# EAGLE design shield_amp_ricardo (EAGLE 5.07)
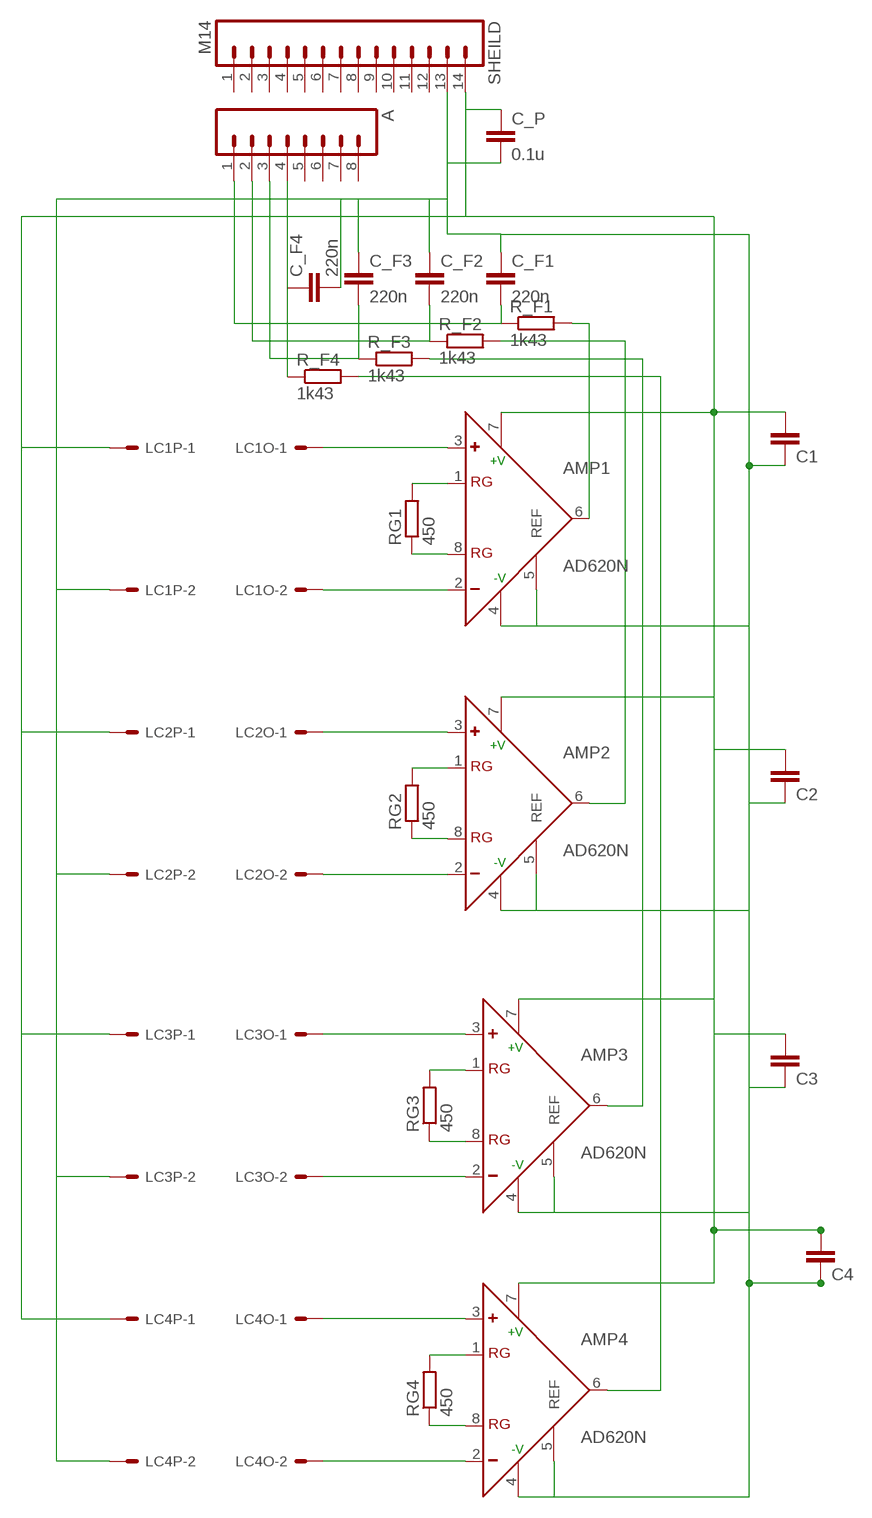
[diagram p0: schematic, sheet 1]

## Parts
A  M081X08  [1X08]
AMP1  AD620N  [DIL08]
AMP2  AD620N  [DIL08]
AMP3  AD620N  [DIL08]
AMP4  AD620N  [DIL08]
C1  C-EUC0603  [C0603]
C2  C-EUC0603  [C0603]
C3  C-EUC0603  [C0603]
C4  C-EUC0603  [C0603]
C_F1  220n  C-EU025-024X044  [C025-024X044]
C_F2  220n  C-EU025-024X044  [C025-024X044]
C_F3  220n  C-EU025-024X044  [C025-024X044]
C_F4  220n  C-EU025-024X044  [C025-024X044]
C_P  0.1u  C-EU025-024X044  [C025-024X044]
LC1O  87758-0216  [87758-0216]
LC1P  87758-0216  [87758-0216]
LC2O  87758-0216  [87758-0216]
LC2P  87758-0216  [87758-0216]
LC3O  87758-0216  [87758-0216]
LC3P  87758-0216  [87758-0216]
LC4O  87758-0216  [87758-0216]
LC4P  87758-0216  [87758-0216]
R_F1  1k43  R-EU_0207/7  [0207/7]
R_F2  1k43  R-EU_0207/7  [0207/7]
R_F3  1k43  R-EU_0207/7  [0207/7]
R_F4  1k43  R-EU_0207/7  [0207/7]
RG1  450  R-EU_0207/7  [0207/7]
RG2  450  R-EU_0207/7  [0207/7]
RG3  450  R-EU_0207/7  [0207/7]
RG4  450  R-EU_0207/7  [0207/7]
SHEILD  M14  [1X14]

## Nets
GND: AMP1.4(-V) AMP1.5(REF) AMP2.4(-V) AMP2.5(REF) AMP3.4(-V) AMP3.5(REF) AMP4.4(-V) AMP4.5(REF) C1.1 C2.1 C3.1 C4.1 C_F1.1 C_F2.1 C_F3.1 C_F4.2 C_P.2 LC1P.2 LC2P.2 LC3P.2 LC4P.2 SHEILD.13
N$1: AMP1.1(RG) RG1.2
N$2: AMP1.3(+) LC1O.1
N$3: AMP1.8(RG) RG1.1
N$4: AMP1.2(-) LC1O.2
N$5: AMP2.3(+) LC2O.1
N$6: AMP2.1(RG) RG2.2
N$7: AMP2.8(RG) RG2.1
N$8: AMP2.2(-) LC2O.2
N$9: AMP3.3(+) LC3O.1
N$10: AMP3.1(RG) RG3.2
N$11: AMP3.8(RG) RG3.1
N$12: AMP3.2(-) LC3O.2
N$13: AMP4.3(+) LC4O.1
N$14: AMP4.1(RG) RG4.2
N$15: AMP4.8(RG) RG4.1
N$16: AMP4.2(-) LC4O.2
N$17: AMP1.6(OUT) R_F1.2
N$18: AMP2.6(OUT) R_F2.2
N$19: AMP3.6(OUT) R_F3.2
N$20: AMP4.6(OUT) R_F4.2
N$22: A.3 C_F3.2 R_F3.1
N$23: A.1 C_F1.2 R_F1.1
N$25: A.2 C_F2.2 R_F2.1
N$26: A.4 C_F4.1 R_F4.1
VCC: AMP1.7(+V) AMP2.7(+V) AMP3.7(+V) AMP4.7(+V) C1.2 C2.2 C3.2 C4.2 C_P.1 LC1P.1 LC2P.1 LC3P.1 LC4P.1 SHEILD.14
Unconnected: A.5 A.6 A.7 A.8 SHEILD.1 SHEILD.2 SHEILD.3 SHEILD.4 SHEILD.5 SHEILD.6 SHEILD.7 SHEILD.8 SHEILD.9 SHEILD.10 SHEILD.11 SHEILD.12

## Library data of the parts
A = SparkFun:M08: Header 8 Standard 8-pin 0.1" header. Use with straight break away headers (SKU : PRT-00116), right angle break away headers (PRT-00553), swiss pins (PRT-00743), machine pins (PRT-00117), and female headers (PRT-00115).
AMP1-AMP4 = analog-devices:AD620: Low Cost, Low Power, Instrumentation Amplifier Source: http://www.analog.com/UploadedFiles/Data_Sheets/37793330023930AD620_e.pdf
C1-C4 C_F1-C_F4 C_P = resistor:C-EU: CAPACITOR, European symbol
LC1O LC1P LC2O LC2P LC3O LC3P LC4O LC4P = con-molex:87758-0216: 2 Pin - 2mm Dual Row Single Wafer, Vertical T/H HDR
R_F1-R_F4 RG1-RG4 = resistor:R-EU_: RESISTOR, European symbol
SHEILD = SparkFun:M14: Header 14 Standard 14-pin 0.1" header. Use with straight break away headers (SKU : PRT-00116), right angle break away headers (PRT-00553), swiss pins (PRT-00743), machine pins (PRT-00117), and female headers (PRT-00115).

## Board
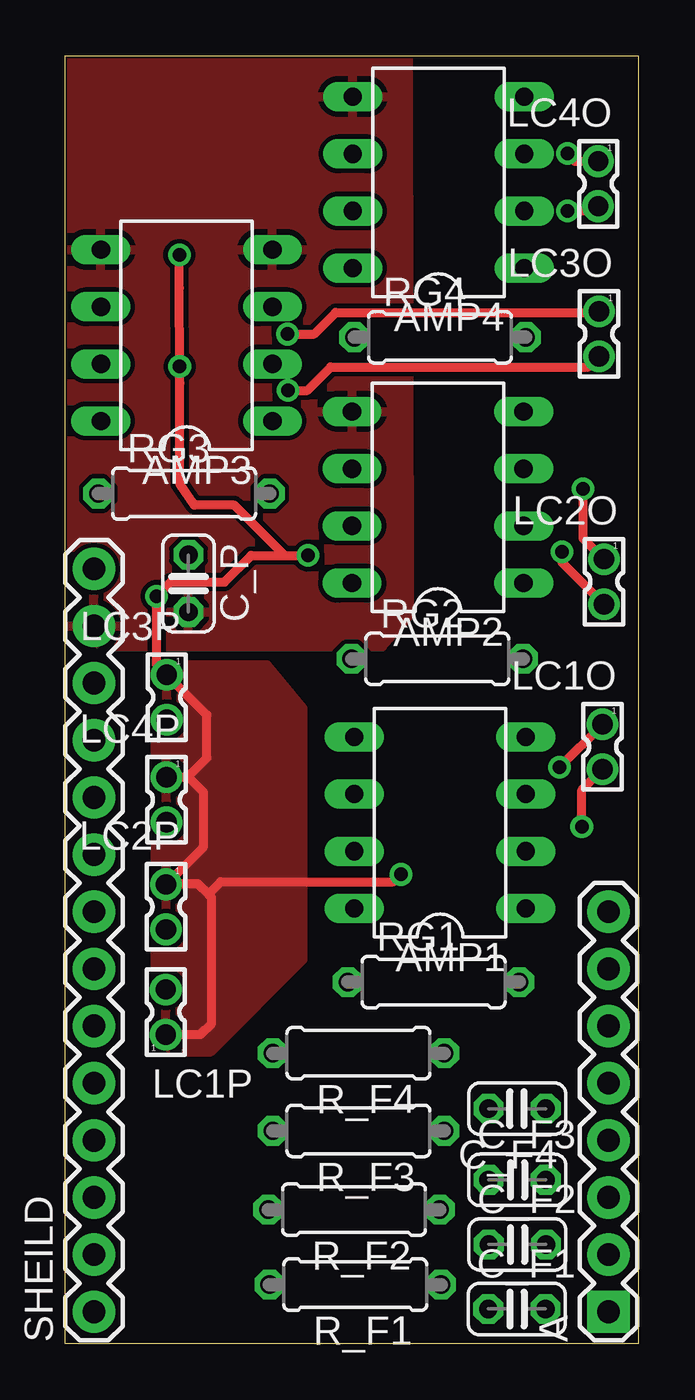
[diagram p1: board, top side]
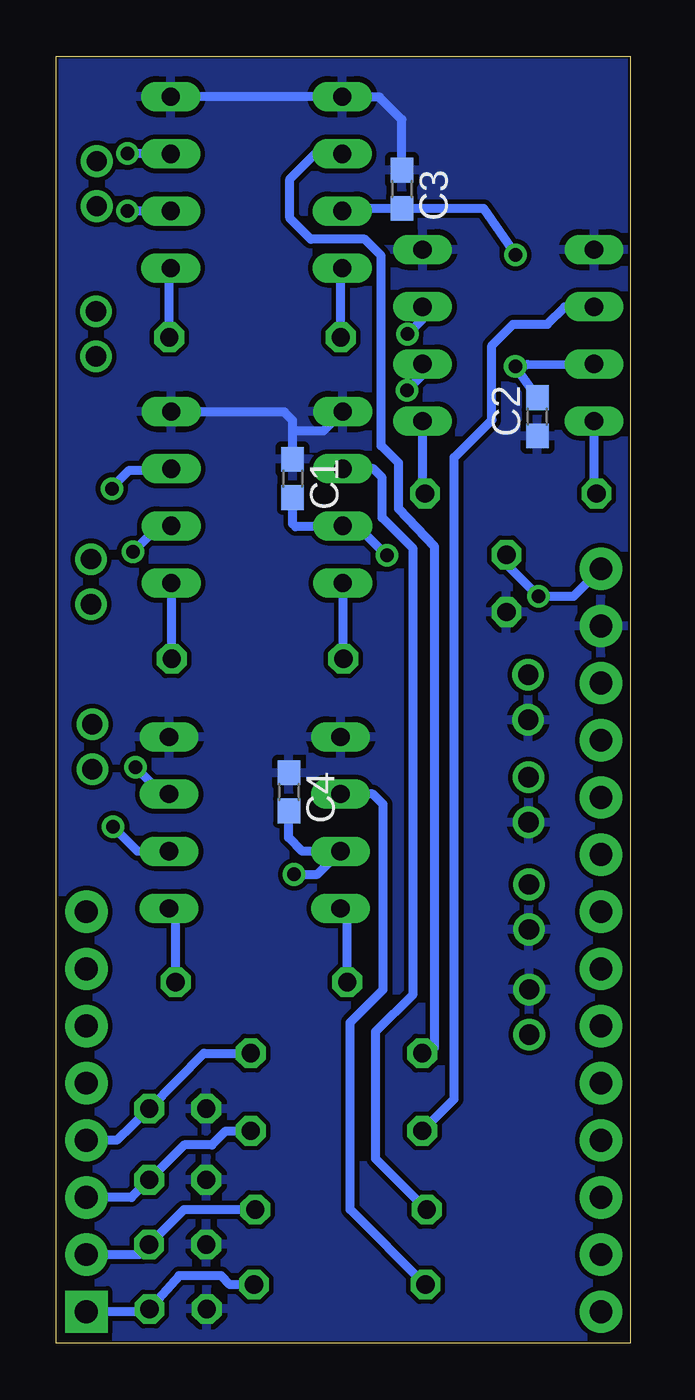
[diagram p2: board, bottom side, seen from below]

Size 25.5 x 57.2 mm. Coordinates in mm from the lower left corner, seen from the top.
Outline: 0,0 25.5,0 25.5,57.2 0,57.2 0,0
Copper layers (1*16): Top 0.035mm / dielectric 1.5mm / Bottom 0.035mm
Design rules "default *": minimum track width 10mil, minimum drill 24mil, track to track 8mil, track to pad 8mil, pad to pad 8mil, via to via 8mil, smd to smd 8mil, copper to edge 4mil, drill to drill 8mil, minimum pad ring 10mil, minimum via ring 8mil, stop-mask expansion 4mil, vias tented up to drill 0mil, thermal gap 10mil

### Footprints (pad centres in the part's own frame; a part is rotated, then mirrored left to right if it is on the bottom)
1X08 = drill 1.016 pad 1.88 square: 1 0,0 | drill 1.016 pad 1.88 round: 2 2.54,0; 3 5.08,0; 4 7.62,0; 5 10.16,0; 6 12.7,0; 7 15.24,0; 8 17.78,0
DIL08 = drill 0.813 long: 1 -3.81,-3.81; 2 -1.27,-3.81; 3 1.27,-3.81; 4 3.81,-3.81; 5 3.81,3.81; 6 1.27,3.81; 7 -1.27,3.81; 8 -3.81,3.81
C0603 = smd 1.1 x 1: 1 -0.85,0; 2 0.85,0
C025-024X044 = drill 0.813 octagon: 1 -1.27,0; 2 1.27,0
87758-0216 = drill 0.9 pad 1.27 round: 1 0,-1; 2 0,1
0207/7 = drill 0.813 octagon: 1 -3.81,0; 2 3.81,0
1X14 = drill 1.016 pad 1.88 round: 1 0,0; 2 2.54,0; 3 5.08,0; 4 7.62,0; 5 10.16,0; 6 12.7,0; 7 15.24,0; 8 17.78,0; 9 20.32,0; 10 22.86,0; 11 25.4,0; 12 27.94,0; 13 30.48,0; 14 33.02,0

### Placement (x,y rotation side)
A  24.16,1.4 90 top
AMP1  16.68,23.14 90 top
AMP2  16.58,37.6 90 top
AMP3  5.42,44.8 90 top
AMP4  16.6,51.59 90 top
C1  15,38.44 270 bottom
C2  4.13,41.18 90 bottom
C3  10.14,51.28 270 bottom
C4  15.17,24.5 270 bottom
C_F1  20.08,1.52 0 top
C_F2  20.11,4.39 0 top
C_F3  20.1,7.26 0 top
C_F4  20.1,10.43 180 top
C_P  5.5,33.77 270 top
LC1O  23.9,26.51 180 top
LC1P  4.49,14.72 0 top
LC2O  23.95,33.85 180 top
LC2P  4.5,19.4 180 top
LC3O  23.73,44.86 180 top
LC3P  4.53,28.71 180 top
LC4O  23.7,51.53 180 top
LC4P  4.52,24.15 180 top
R_F1  12.91,2.6 180 top
R_F2  12.85,5.94 180 top
R_F3  13.05,9.44 180 top
R_F4  13.05,12.89 180 top
RG1  16.39,16.05 0 top
RG2  16.55,30.42 0 top
RG3  5.3,37.76 0 top
RG4  16.67,44.71 0 top
SHEILD  1.3,1.4 90 top

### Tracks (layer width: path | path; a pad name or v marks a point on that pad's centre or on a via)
GND
  Top 0.406: C_F3.1 | C_F4.2
  Bottom 0.406: AMP2.5 13.62,40.56 14.88,40.56 15,40.44 | C1.1 15,40.44 | AMP2.4 20.37,41.39 15.37,41.39 15,41.02 15,40.44 | C3.1 10.14,54.39 11.14,55.39 AMP4.5 AMP4.4
  pour Bottom: -0.99,57.87 -1.12,57.87 -1.12,-1.16 26.14,-1.16 26.14,57.74
  pour Top: -0.55,57.58 -0.5,31.69 1.91,30.98 14.11,30.96 15.34,32.37 15.29,57.23 14.87,57.65
N$1
  Bottom 0.406: AMP1.1 20.2,19.04 RG1.2
N$2  (via drill 0.6)
  Top 0.406: v21.98,25.59 LC1O.1
  Bottom 0.406: v21.98,25.59 20.8,24.41 AMP1.3
N$3
  Bottom 0.406: AMP1.8 12.58,19.04 RG1.1
N$4  (via drill 0.6)
  Top 0.406: LC1O.2 22.97,24.59 v22.97,22.96
  Bottom 0.406: v22.97,22.96 21.88,21.87 AMP1.2
N$5  (via drill 0.6)
  Top 0.406: LC2O.1 23.03,35.77 v23.03,37.98
  Bottom 0.406: v23.03,37.98 23.03,38.03 22.26,38.8 20.46,38.8 AMP2.3
N$6
  Bottom 0.406: AMP2.1 20.37,33.76 RG2.2
N$7
  Bottom 0.406: AMP2.8 12.74,33.76 RG2.1
N$8  (via drill 0.6)
  Top 0.406: LC2O.2 22.1,34.71 v22.1,35.17
  Bottom 0.406: v22.1,35.17 20.94,36.33 AMP2.2
N$9  (via drill 0.6)
  Top 0.406: 23.52,46.07 LC3O.1 23.69,45.81 12.03,45.81 11.08,44.85 v9.89,44.85
  Bottom 0.406: AMP3.3 9.23,45.52 v9.89,44.85
N$10
  Bottom 0.406: AMP3.1 9.23,37.88 RG3.2
N$11
  Bottom 0.406: AMP3.8 1.6,37.88 RG3.1
N$12  (via drill 0.6)
  Top 0.406: 23.41,43.53 LC3O.2 23.27,43.39 11.81,43.39 10.77,42.34 v9.92,42.34
  Bottom 0.406: AMP3.2 9.23,43.04 v9.92,42.34
N$13  (via drill 0.6)
  Top 0.406: LC4O.1 22.68,52.53 v22.34,52.88
  Bottom 0.406: v22.34,52.88 20.43,52.88 AMP4.3
N$14
  Bottom 0.406: AMP4.1 20.48,47.71 RG4.2
N$15
  Bottom 0.406: AMP4.8 12.86,47.71 RG4.1
N$16  (via drill 0.6)
  Top 0.406: v22.34,50.33 23.49,50.33 LC4O.2
  Bottom 0.406: AMP4.2 v22.33,50.32 v22.34,50.33
N$17
  Bottom 0.406: AMP1.6 11.44,24.41 10.98,23.95 10.98,15.72 12.44,14.26 12.44,5.95 R_F1.2
N$18
  Bottom 0.406: AMP2.6 11.41,38.87 11.02,38.47 11.02,36.69 9.64,35.31 9.64,15.51 11.31,13.85 11.31,8.2 R_F2.2
N$19
  Bottom 0.406: R_F3.2 7.82,10.86 7.82,39.37 6.2,40.99 | AMP3.6 2.91,46.06 3.68,45.29 5.2,45.29 6.15,44.34 6.15,41.04 6.2,40.99 | 6.2,40.99
N$20
  Bottom 0.406: R_F4.2 8.69,13.15 8.69,35.4 10.29,37.09 10.29,39.12 11.06,39.89 11.06,48.33 11.79,49.06 14.19,49.06 15.12,49.99 15.12,51.74 13.99,52.86 AMP4.6
N$22
  Bottom 0.406: A.3 22.16,6.48 C_F3.2 19.82,8.81 18.59,8.81 17.96,9.44 R_F3.1
N$23
  Bottom 0.406: A.1 21.64,1.4 C_F1.2 20.04,3 18.18,3 17.78,2.6 R_F1.1
N$25
  Bottom 0.406: A.2 21.83,3.94 C_F2.2 19.83,5.94 R_F2.1
N$26
  Bottom 0.406: A.4 22.81,9.02 C_F4.1 18.94,12.89 R_F4.1
VCC  (via drill 0.6)
  Top 0.406: LC1P.1 6.03,13.72 6.52,14.22 6.52,19.81 6.42,19.91 | 6.42,19.91 5.91,20.42 4.53,20.42 | 4.53,20.42 LC2P.1 | v14.93,20.84 14.6,20.5 6.93,20.5 6.42,20 6.42,19.91 | 4.53,20.42 6.17,22.07 6.17,24.49 5.51,25.15 | 5.51,25.15 LC4P.1 | v4.08,33.2 4.08,30.17 LC3P.1 6.32,27.93 6.32,26.02 5.51,25.21 5.51,25.15 | v4.08,33.2 4.44,33.56 | v4.08,33.2 4.7,33.83 7.09,33.83 8.28,35.01 9.77,35.01 | v4.08,33.2 4.12,33.25 | v5.09,48.37 5.09,46.9 v5.11,43.41 5.11,42.65 5.11,38.18 5.76,37.25 7.54,37.25 9.77,35.01 | 9.77,35.01 v10.81,35.01
  Bottom 0.406: C1.2 15,36.42 14.87,36.29 12.81,36.29 AMP2.7 12.13,36.33 v10.81,35.01 | AMP4.7 12.68,50.43 C3.2 6.51,50.43 v5.09,48.37 | C4.2 15.17,22.47 14.57,21.87 AMP1.7 13.9,20.84 v14.93,20.84 | C_P.1 5.5,34.62 v4.08,33.2 2.52,33.2 SHEILD.14 | AMP3.7 4.57,43.5 v5.11,43.41 C2.2
  pour Top: 3.99,30.15 3.99,13.78 4.81,12.96 6.5,12.96 10.59,17.05 10.59,28.22 8.99,30.15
